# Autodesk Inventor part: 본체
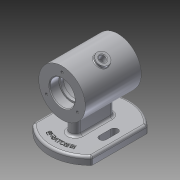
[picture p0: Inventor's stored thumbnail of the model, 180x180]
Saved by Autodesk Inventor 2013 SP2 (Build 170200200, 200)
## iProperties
Created: 2022-02
Part Number: 본체
Material: 알루미늄 6061
Document SubType Name: Modeling
Designer: a
Mass: 497.103 g
Surface Area: 489.735 cm^2
Volume: 183.433 cm^3
Density: 2.71 g/cm^3
Author: a
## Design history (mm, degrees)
sketch "스케치1"
  geometry: L1 (-36, 0)-(36, 0); L2 (-36, 0)-(-36, 30); L3 (-36, 30)-(36, 30); L4 (36, 30)-(36, 0); L5 (-36, 16)-(-24, 16); L6 (-24, 16)-(-24, 14); L7 (-24, 14)-(-20, 14); L8 (-20, 14)-(-20, 25); L9 (-20, 25)-(20, 25); L10 (20, 25)-(20, 14); L11 (20, 14)-(24, 14); L12 (24, 14)-(24, 16); L13 (24, 16)-(36, 16); 2 further points
  constraints: 26 end point, 7 parallel, 5 perpendicular, 2 point on line, 1 coincident, 1 collinear, 1 horizontal, 1 midpoint
  dimensions: "d0" = 72 distance of L1.start L1.end; "d1" = 60 diameter of L3 L1; "d2" = 32 diameter of L5 L1; "d3" = 32 diameter of L13 L1; "d4" = 28 diameter of L7 L1; "d5" = 50 diameter of L9 L1; "d6" = 28 diameter of L11 L1; "d7" = 12 distance of L5.start L5.end; "d8" = 12 distance of L12.end L13.end; "d9" = 40 distance of L8.end L9.end
revolve "회전1" sketch "스케치1" stored, may be unused: angle "d10" = 90 deg
node "작업 평면1"
sketch "스케치2"
  geometry: L1 (35.496, -38)-(-35.496, -38); L2 (35.496, 38)-(-35.496, 38); A1 r 52 centre (0, 0) between (35.496, -38) and (-35.496, -38); 1 further point
  constraints: 4 end point, 4 point on circle, 1 centre point, 1 coincident, 1 horizontal, 1 parallel
  dimensions: "d12" = 104 diameter of A1; "d13" = 38 distance from line of A1.centre L1; "d14" = 38 distance from line of point (0, 0) L2
extrude "돌출1" join sketch "스케치2" distance "d15" = 10; taper "d16" = 0 deg
sketch "스케치3"
  geometry: L1 (-19, 7)-(19, 7); L2 (19, 7)-(19, -7); L3 (19, -7)-(-19, -7); L4 (-19, -7)-(-19, 7); A1 r 52 centre (0, 0) between (-35.496, 38) and (-35.496, -38) reference; A2 r 7 centre (-19, 0) between (-19, 7) and (-19, -7); A3 r 7 centre (19, 0) between (19, -7) and (19, 7); 1 further point
  constraints: 8 end point, 4 point on circle, 3 midpoint, 2 centre point, 2 parallel, 1 horizontal, 1 horizontal alignment, 1 perpendicular, 1 vertical alignment
  dimensions: "d20" = 38 distance of L2.end L3.end; "d21" = 14 distance of L1.end L2.end
extrude "돌출2" join sketch "스케치3" stored distance "d22" = 10; taper "d23" = 0 deg
sketch "스케치4"
  geometry: L1 (-7.5, 28.5)-(7.5, 28.5); L2 (7.5, 28.5)-(7.5, 19.5); L3 (7.5, 19.5)-(-7.5, 19.5); L4 (-7.5, 19.5)-(-7.5, 28.5); A1 r 52 centre (0, 0) between (-35.496, 38) and (-35.496, -38) reference; A2 r 52 centre (0, 0) between (35.496, -38) and (35.496, 38) reference; A3 r 4.5 centre (-7.5, 24) between (-7.5, 28.5) and (-7.5, 19.5); A4 r 4.5 centre (7.5, 24) between (7.5, 19.5) and (7.5, 28.5); 1 further point
  constraints: 8 end point, 4 point on circle, 3 midpoint, 2 centre point, 2 parallel, 1 horizontal, 1 perpendicular, 1 vertical alignment
  dimensions: "d24" = 15 distance of L2.end L3.end; "d25" = 9 distance of L1.end L2.end; "d26" = 24 vertical distance of A2.centre A3.centre
extrude "돌출3" cut sketch "스케치4" stored distance "d27" = 10; taper "d28" = 0 deg
fillet "모깎기1" dims "d29" = 0.3, "d30" = 3
sketch "스케치5"
  geometry: L1 (0, 0)-(28.579, 16.5); L2 (0, 0)-(33, 0); 1 further point
  constraints: 4 end point, 1 coincident, 1 equal length, 1 horizontal
  dimensions: "d31" = 33 distance of L1.start L1.end; "d32" = 30 deg angle of L2 L1
node "작업 평면2"
sketch "스케치6"
  geometry: C1 r 8 at (0, 0); 1 further point
  constraints: 1 centre point, 1 coincident
  dimensions: "d33" = 16 diameter of C1
extrude "돌출4" join sketch "스케치6" stored distance "d34" = 10; taper "d35" = 0 deg
sketch "스케치7"
  geometry: C1 r 8 at (0, 0) reference; 1 further point
  constraints: 1 coincident
hole "구멍1" sketch "스케치7" at (0, 0) diameter "d36" = 8; stored, may be unused: countersink angle "d40" = 90 deg, drill point angle "d42" = 118 deg; dims "d37" = 6, "d38" = 4, "d39" = 2, "d41" = 8
fillet "모깎기2" dims "d43" = 1
fillet "모깎기3" dims "d44" = 1
sketch "스케치8"
  geometry: C1 r 30 at (0, 0) reference; 1 further point
  constraints: 1 vertical alignment
  dimensions: "d45" = 23 distance of point (0, 23) C1.centre
hole "구멍2" sketch "스케치8" at (0, 23) diameter "d46" = 3.242; stored, may be unused: countersink angle "d50" = 90 deg, drill point angle "d52" = 118 deg; dims "d47" = 8, "d48" = 4, "d49" = 2, "d51" = 10
sketch "스케치9"
  geometry: C1 r 42.5 at (0, 0); A1 r 52 centre (0, 0) between (35.496, -38) and (35.496, 38) reference
  constraints: 1 centre point, 1 coincident, 1 other
  dimensions: "d56" = 85 diameter of C1
feature "엠보싱1" sketch "스케치9" dims "d0" = 72, "d1" = 60, "d2" = 32, "d3" = 32, "d4" = 28, "d5" = 50, "d6" = 28, "d7" = 12, "d8" = 12, "d9" = 40, "d14" = 38, "d57" = 0.5, "d58" = 0
fillet "모깎기4" dims "d59" = 3
fillet "모깎기5" dims "d60" = 3
fillet "모깎기6" dims "d61" = 3
chamfer "모따기1" distance "d62" = 1; stored, may be unused: second distance "d63" = 2, angle "d64" = 45 deg
node "솔리드1"
mirror "대칭1"
pattern_circular "원형 패턴1" dims angle "d54" = 360 deg
mirror "대칭2"
other parameters: "d11" = -62
